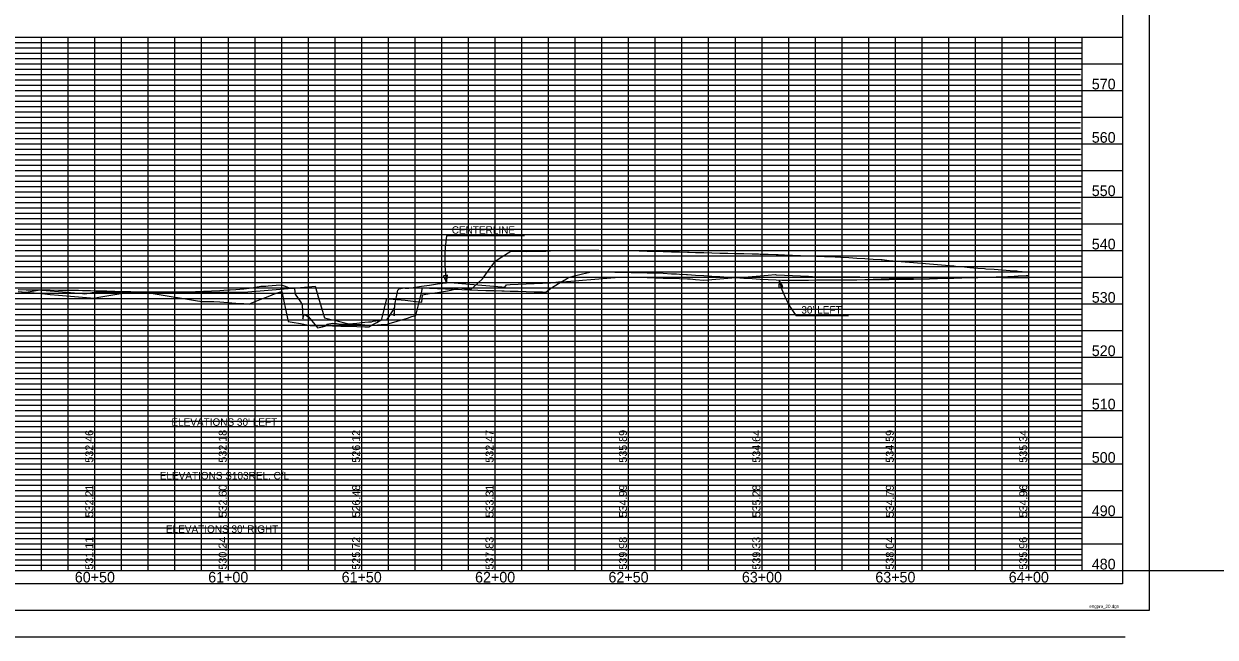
# Model space of a CAD drawing. Extents: x 178884 to 181858, y 178732 to 179192.
# Drawn here: x 179181.1 to 179627.5, y 178732.4 to 178962.4 of the extents above; entities that cross this region are included whole.
import ezdxf

# ---------------------------------------------------------------- set-up
doc = ezdxf.new("R2010")
doc.units = 0
for name, color, linetype in [('RD_DDB_ElevTX', 7, 'Continuous'), ('RD_DDB_Profile_EX', 7, 'Continuous'), ('RD_DDB_StaTX', 7, 'Continuous'), ('RD_DDB_StripGrade', 7, 'Continuous'), ('RD_GPK_Profile_Cell', 7, 'Continuous'), ('RD_SHT_Bndy', 7, 'Continuous'), ('RD_SHT_IplotShp', 7, 'Continuous'), ('RD_SHT_MjGrid', 7, 'Continuous'), ('RD_SHT_MnGrid', 7, 'Continuous'), ('RD_SHT_SubGrid', 7, 'Continuous'), ('RD_SHT_TX', 7, 'Continuous'), ('RD_TX_Profile', 7, 'Continuous')]:
    doc.layers.add(name, color=color, linetype=linetype)

msp = doc.modelspace()

# ---------------------------------------------------------------- linework, layer by layer
at = {"layer": 'RD_DDB_Profile_EX'}
for points in [[(179342.12, 178862.82), (179344.19, 178863.42), (179345.14, 178863.28), (179348.16, 178862.84), (179348.58, 178862.78), (179351.19, 178865.18), (179352.91, 178866.77), (179354.21, 178868.52), (179357.23, 178872.6), (179358.02, 178873.67), (179360.25, 178875.06), (179363.54, 178877.12), (179364.34, 178877.12), (179366.3, 178877.09), (179369.32, 178877.06), (179372.35, 178877.08), (179375.37, 178877.1), (179376.73, 178877.11), (179378.39, 178877.23), (179380.1, 178877.37), (179381.41, 178877.39), (179384.44, 178877.45), (179387.46, 178877.5), (179390.75, 178877.56), (179393.51, 178877.53), (179396.53, 178877.49), (179399.55, 178877.45), (179402.57, 178877.41), (179403.51, 178877.4), (179405.11, 178877.43), (179405.6, 178877.42), (179408.62, 178877.33), (179411.64, 178877.25), (179414.67, 178877.17), (179417.69, 178877.08), (179420.71, 178877), (179423.74, 178876.92), (179426.76, 178876.84), (179429.78, 178876.76), (179430.37, 178876.74), (179432.8, 178876.68), (179435.83, 178876.6), (179438.85, 178876.52), (179441.87, 178876.45), (179444.9, 178876.37), (179447.36, 178876.31), (179447.92, 178876.3), (179450.94, 178876.22), (179453.96, 178876.15), (179454.75, 178876.13), (179456.39, 178876.09), (179456.99, 178876.07), (179460.01, 178875.98), (179463.03, 178875.88), (179463.7, 178875.86), (179466.06, 178875.77), (179469.08, 178875.65), (179472.1, 178875.54), (179475.12, 178875.42), (179478.15, 178875.3), (179481.17, 178875.19), (179482.28, 178875.15), (179482.99, 178875.13), (179484.19, 178875.08), (179485.13, 178875.04), (179487.22, 178874.91), (179490.24, 178874.73), (179493.26, 178874.54), (179496.28, 178874.37), (179499.31, 178874.19), (179502.33, 178874.02), (179502.73, 178874), (179504.43, 178873.79), (179505.35, 178873.7), (179508.38, 178873.41), (179511.4, 178873.14), (179514.42, 178872.87), (179517.45, 178872.61), (179520.47, 178872.35), (179523.49, 178872.1), (179526.51, 178871.85), (179529.54, 178871.6), (179530.22, 178871.55), (179532.56, 178871.34), (179535.58, 178871.07), (179538.61, 178870.81), (179541.07, 178870.61), (179541.63, 178870.56), (179544.65, 178870.33), (179547.67, 178870.11), (179550.7, 178869.89), (179553.2, 178869.71), (179553.72, 178869.66), (179556.74, 178869.39), (179557.57, 178869.31)], [(179330.03, 178863.97), (179333.05, 178864.4), (179336.07, 178864.84), (179339.09, 178865.27), (179339.45, 178865.32), (179340.34, 178865.42), (179342.33, 178865.21), (179345.14, 178864.99), (179348.16, 178864.76), (179351.19, 178864.52), (179354.21, 178864.28), (179357.23, 178864.03), (179360.25, 178863.79), (179361.35, 178863.7), (179361.95, 178864.53), (179363.28, 178864.6), (179366.3, 178864.74), (179369.32, 178864.89), (179372.35, 178865.03), (179375.37, 178865.18), (179378.39, 178865.32), (179381.41, 178865.6), (179384.44, 178865.8), (179387.65, 178866.02), (179390.48, 178866.26), (179393.51, 178866.52), (179396.53, 178866.78), (179399.55, 178867.04), (179402.68, 178867.3), (179405.6, 178867.34), (179408.62, 178867.38), (179411.14, 178867.42), (179411.64, 178867.4), (179414.67, 178867.29), (179417.69, 178867.18), (179420.71, 178867.07), (179423.74, 178866.96), (179426.76, 178866.85), (179429.78, 178866.74), (179430.71, 178866.71), (179432.8, 178866.55), (179435.83, 178866.32), (179438.85, 178866.55), (179441.87, 178866.77), (179444.9, 178867), (179447.92, 178867.22), (179450.94, 178867.45), (179453.96, 178867.68), (179456.99, 178867.91), (179460.01, 178868.14), (179462.68, 178868.34), (179463.03, 178868.32), (179466.06, 178868.17), (179469.08, 178868.02), (179472.1, 178867.87), (179475.12, 178867.72), (179478.15, 178867.57), (179479.22, 178867.52), (179481.17, 178867.52), (179484.19, 178867.51), (179487.22, 178867.5), (179490.24, 178867.49), (179493.26, 178867.49), (179494.33, 178867.48), (179496.28, 178867.41), (179499.31, 178867.28), (179502.33, 178867.16), (179505.35, 178867.04), (179506.36, 178867), (179508.38, 178866.97), (179511.4, 178866.92), (179514.42, 178866.87), (179517.45, 178866.82), (179518.53, 178866.81), (179520.47, 178866.86), (179523.49, 178866.95), (179526.51, 178867.04), (179529.54, 178867.13), (179532.56, 178867.22), (179535.58, 178867.32), (179538.11, 178867.39), (179538.61, 178867.39), (179541.63, 178867.36), (179544.65, 178867.33), (179547.67, 178867.3), (179550.87, 178867.26), (179553.72, 178867.28), (179556.74, 178867.31), (179557.57, 178867.31)], [(179376.69, 178861.83), (179378.39, 178863.17), (179378.75, 178863.45), (179381.41, 178865.01), (179384.44, 178866.78), (179385.58, 178867.45), (179387.46, 178867.91), (179390.48, 178868.66), (179393.81, 178869.42), (179394.31, 178869.43), (179396.53, 178869.39), (179399.55, 178869.33), (179402.57, 178869.27), (179405.6, 178869.21), (179408.62, 178869.16), (179411.64, 178869.1), (179414.67, 178869.04), (179417.69, 178868.99), (179418.31, 178868.98), (179420.71, 178868.85), (179423.74, 178868.69), (179425.63, 178868.59), (179426.76, 178868.53), (179429.42, 178868.38), (179429.78, 178868.36), (179432.8, 178868.18), (179435.83, 178867.99), (179438.85, 178867.81), (179441.87, 178867.62), (179444.9, 178867.44), (179447.92, 178867.25), (179450.94, 178867.07), (179453.96, 178866.88), (179456.99, 178866.7), (179460.01, 178866.52), (179463.03, 178866.34), (179465.11, 178866.21), (179466.06, 178866.22), (179468.16, 178866.25), (179469.08, 178866.25), (179472.1, 178866.28), (179475.12, 178866.31), (179478.15, 178866.33), (179481.17, 178866.36), (179484.19, 178866.38), (179487.22, 178866.41), (179490.24, 178866.43), (179493.26, 178866.45), (179496.28, 178866.48), (179497.75, 178866.49), (179499.31, 178866.5), (179502.33, 178866.52), (179505.36, 178866.55), (179508.38, 178866.58), (179511.4, 178866.62), (179513.52, 178866.64), (179514.42, 178866.67), (179517.45, 178866.74), (179520.47, 178866.82), (179523.49, 178866.9), (179526.51, 178866.98), (179529.54, 178867.06), (179532.56, 178867.14), (179535.58, 178867.22), (179538.61, 178867.3), (179541.63, 178867.37), (179544.65, 178867.45), (179545.48, 178867.47), (179547.79, 178867.53), (179548.13, 178867.52), (179549.85, 178867.64), (179550.7, 178867.68), (179553.72, 178867.86), (179556.74, 178868.03), (179557.57, 178868.07)], [(179178.88, 178862.74), (179181.9, 178862.7), (179184.93, 178862.67), (179187.95, 178862.63), (179190.97, 178862.59), (179193.99, 178862.56), (179197.02, 178862.52), (179200.04, 178862.48), (179201.49, 178862.47), (179203.06, 178862.43), (179206.09, 178862.36), (179209.11, 178862.29), (179212.13, 178862.21), (179215.15, 178862.14), (179218.18, 178862.07), (179221.2, 178861.99), (179222.93, 178861.95), (179224.22, 178861.95), (179227.25, 178861.94), (179230.27, 178861.92), (179233.29, 178861.91), (179236.32, 178861.9), (179237.91, 178861.89), (179239.34, 178861.88), (179242.36, 178861.86), (179245.38, 178861.84), (179248.41, 178861.82), (179251.43, 178861.79), (179254.45, 178861.77), (179257.48, 178861.75), (179260.5, 178861.73), (179262.7, 178861.73), (179263.02, 178861.75), (179263.52, 178861.79), (179266.54, 178862.04), (179269.57, 178862.29), (179272.59, 178862.55), (179275.61, 178862.8), (179278.64, 178863.05), (179281.66, 178863.3), (179284.68, 178863.56), (179287.7, 178863.81), (179290.22, 178864.02), (179290.73, 178862.23), (179291.35, 178860.04), (179293.75, 178852.1), (179296.77, 178851.44), (179297.48, 178851.29), (179299.8, 178850.63), (179302.82, 178849.84), (179305.84, 178849.71), (179308.86, 178849.58), (179312.15, 178849.44), (179314.91, 178849.59), (179316.91, 178849.69), (179317.93, 178849.99), (179320.96, 178850.9), (179323.98, 178851.81), (179324.85, 178852.07), (179326.51, 178852.59), (179327, 178852.73), (179327.99, 178853), (179330.03, 178861.57), (179330.45, 178863.38), (179333.05, 178863.28), (179336.07, 178863.16), (179339.09, 178863.03), (179342.12, 178862.91), (179345.14, 178862.79), (179348.16, 178862.66), (179351.19, 178862.54), (179354.21, 178862.42), (179354.81, 178862.39), (179356.41, 178862.38), (179357.23, 178862.35), (179360.25, 178862.26), (179361.09, 178862.23), (179363.28, 178862.18), (179366.3, 178862.1), (179369.32, 178862.02), (179372.35, 178861.94), (179375.37, 178861.86), (179376.69, 178861.83)], [(179180.16, 178861.5), (179181.9, 178861.78), (179184.93, 178862.26), (179187.21, 178862.63), (179187.95, 178862.57), (179190.97, 178862.3), (179193.99, 178862.04), (179197.02, 178861.78), (179200.04, 178861.52), (179203.06, 178861.26), (179203.9, 178861.19), (179206.09, 178861.56), (179208.03, 178861.89), (179209.11, 178861.89), (179212.13, 178861.87), (179215.15, 178861.86), (179218.18, 178861.85), (179221.2, 178861.83), (179224.48, 178861.82), (179227.25, 178861.81), (179230.27, 178861.79), (179233.29, 178861.78), (179235.9, 178861.77), (179236.32, 178861.77), (179239.34, 178861.75), (179240.61, 178861.74), (179242.36, 178861.83), (179245.38, 178861.98), (179248.41, 178862.13), (179251.43, 178862.29), (179254.45, 178862.44), (179257.48, 178862.59), (179258.41, 178862.64), (179260.5, 178862.79), (179263.52, 178863.02), (179264.56, 178863.09), (179266.54, 178863.42), (179269.83, 178863.96), (179271.73, 178864.07), (179272.59, 178864.13), (179275.61, 178864.35), (179277.45, 178864.48), (179278.64, 178864.08), (179280.88, 178863.31), (179281.66, 178863.28), (179282.55, 178863.25), (179282.59, 178861.66), (179282.78, 178861), (179284.68, 178858.16), (179285.35, 178857.16), (179285.55, 178851.73), (179286.06, 178853.52), (179287.7, 178852.54), (179290.73, 178848.87), (179291.1, 178848.42), (179292.95, 178848.71), (179293.89, 178848.99), (179294.74, 178849.81), (179296.77, 178850.2), (179298.23, 178850.07), (179299.8, 178849.81), (179301.1, 178849.77), (179302.82, 178849.93), (179305.84, 178850.2), (179308.86, 178850.47), (179310.25, 178850.59), (179311.3, 178850.68), (179312.01, 178850.9), (179314.91, 178851.26), (179317.19, 178851.55), (179317.93, 178852.66), (179319.36, 178854.81), (179319.87, 178855.95), (179319.9, 178852.94), (179320.15, 178857.02), (179321.25, 178862.55), (179321.67, 178863.04), (179323.6, 178863.34), (179323.98, 178863.33), (179325.31, 178863.28), (179327, 178863.53), (179330.03, 178863.97)], [(179178.88, 178861.97), (179181.9, 178861.71), (179184.93, 178861.46), (179187.95, 178861.21), (179190.97, 178860.95), (179193.99, 178860.7), (179197.02, 178860.44), (179200.04, 178860.19), (179203.06, 178859.93), (179206.09, 178859.68), (179207.35, 178859.57), (179209.11, 178859.87), (179212.13, 178860.37), (179215.15, 178860.87), (179218.18, 178861.38), (179220.45, 178861.75), (179221.2, 178861.75), (179224.22, 178861.74), (179226.92, 178861.72), (179227.25, 178861.67), (179230.27, 178861.17), (179233.29, 178860.67), (179236.32, 178860.17), (179239.34, 178859.68), (179242.36, 178859.18), (179245.38, 178858.68), (179247.71, 178858.29), (179248.41, 178858.28), (179251.43, 178858.25), (179252.27, 178858.24), (179254.45, 178858.09), (179257.48, 178857.88), (179260.5, 178857.67), (179263.52, 178857.46), (179265.46, 178857.33), (179266.54, 178857.76), (179269.57, 178858.97), (179272.59, 178860.17), (179275.61, 178861.37), (179277.69, 178861.98), (179278.64, 178857.71), (179280.16, 178850.83), (179281.66, 178850.54), (179284.68, 178849.97), (179287.7, 178849.41), (179288.31, 178849.29), (179290.73, 178849.27), (179292.67, 178849.25), (179293.75, 178849.22), (179296.77, 178849.14), (179299.8, 178849.05), (179302.82, 178848.96), (179305.84, 178848.88), (179308.86, 178848.79), (179310.3, 178848.75), (179311.89, 178849.6), (179313.38, 178850.41), (179314.91, 178851.39), (179315.26, 178851.62), (179317.1, 178859.41), (179317.93, 178859.33), (179320.96, 178859.03), (179323.98, 178858.72), (179327, 178858.4), (179330.19, 178858.05), (179330.41, 178860.8), (179333.05, 178861.21), (179336.07, 178861.68), (179339.09, 178862.15), (179341.2, 178862.56), (179342.12, 178862.82)]]:
    msp.add_lwpolyline(points, dxfattribs=at)
at = {"layer": 'RD_GPK_Profile_Cell'}
msp.add_line((178957.57, 178757.39), (181857.57, 178757.39), dxfattribs=at)
at = {"layer": 'RD_SHT_Bndy'}
for p, q in [((178922.77, 178957.39), (179592.77, 178957.39)), ((179577.57, 178957.39), (179577.57, 178757.39)), ((178922.77, 178757.39), (179592.77, 178757.39)), ((179593.83, 178742.39), (178889.83, 178742.39)), ((179593.83, 178732.39), (178889.83, 178732.39))]:
    msp.add_line(p, q, dxfattribs=at)
msp.add_lwpolyline([(178922.77, 179172.39), (179592.77, 179172.39), (179592.77, 178752.39), (178922.77, 178752.39)], close=True, dxfattribs=at)
at = {"layer": 'RD_SHT_IplotShp'}
msp.add_lwpolyline([(178884.41, 179182.39), (179602.77, 179182.39), (179602.77, 178742.39), (178884.41, 178742.39)], close=True, dxfattribs=at)
at = {"layer": 'RD_SHT_MjGrid'}
for p, q in [((179197.57, 178957.39), (179197.57, 178757.39)), ((179217.57, 178957.39), (179217.57, 178757.39)), ((179237.57, 178957.39), (179237.57, 178757.39)), ((179257.57, 178957.39), (179257.57, 178757.39)), ((179277.57, 178957.39), (179277.57, 178757.39)), ((179297.57, 178957.39), (179297.57, 178757.39)), ((179317.57, 178957.39), (179317.57, 178757.39)), ((179337.57, 178957.39), (179337.57, 178757.39)), ((179357.57, 178957.39), (179357.57, 178757.39)), ((179377.57, 178957.39), (179377.57, 178757.39)), ((179397.57, 178957.39), (179397.57, 178757.39)), ((179417.57, 178957.39), (179417.57, 178757.39)), ((179437.57, 178957.39), (179437.57, 178757.39)), ((179457.57, 178957.39), (179457.57, 178757.39)), ((179477.57, 178957.39), (179477.57, 178757.39)), ((179497.57, 178957.39), (179497.57, 178757.39)), ((179517.57, 178957.39), (179517.57, 178757.39)), ((179537.57, 178957.39), (179537.57, 178757.39)), ((179557.57, 178957.39), (179557.57, 178757.39)), ((178922.77, 178937.39), (179592.77, 178937.39)), ((178922.77, 178917.39), (179592.77, 178917.39)), ((178922.77, 178897.39), (179592.77, 178897.39)), ((178922.77, 178877.39), (179592.77, 178877.39)), ((178922.77, 178857.39), (179592.77, 178857.39)), ((178922.77, 178837.39), (179592.77, 178837.39)), ((178922.77, 178817.39), (179592.77, 178817.39)), ((178922.77, 178797.39), (179592.77, 178797.39)), ((178922.77, 178777.39), (179592.77, 178777.39))]:
    msp.add_line(p, q, dxfattribs=at)
at = {"layer": 'RD_SHT_MnGrid'}
for p, q in [((179187.57, 178957.39), (179187.57, 178757.39)), ((179207.57, 178957.39), (179207.57, 178757.39)), ((179227.57, 178957.39), (179227.57, 178757.39)), ((179247.57, 178957.39), (179247.57, 178757.39)), ((179267.57, 178957.39), (179267.57, 178757.39)), ((179287.57, 178957.39), (179287.57, 178757.39)), ((179307.57, 178957.39), (179307.57, 178757.39)), ((179327.57, 178957.39), (179327.57, 178757.39)), ((179347.57, 178957.39), (179347.57, 178757.39)), ((179367.57, 178957.39), (179367.57, 178757.39)), ((179387.57, 178957.39), (179387.57, 178757.39)), ((179407.57, 178957.39), (179407.57, 178757.39)), ((179427.57, 178957.39), (179427.57, 178757.39)), ((179447.57, 178957.39), (179447.57, 178757.39)), ((179467.57, 178957.39), (179467.57, 178757.39)), ((179487.57, 178957.39), (179487.57, 178757.39)), ((179507.57, 178957.39), (179507.57, 178757.39)), ((179527.57, 178957.39), (179527.57, 178757.39)), ((179547.57, 178957.39), (179547.57, 178757.39)), ((179567.57, 178957.39), (179567.57, 178757.39)), ((178922.77, 178947.39), (179592.77, 178947.39)), ((178922.77, 178927.39), (179592.77, 178927.39)), ((178922.77, 178907.39), (179592.77, 178907.39)), ((178922.77, 178887.39), (179592.77, 178887.39)), ((178922.77, 178867.39), (179592.77, 178867.39)), ((178922.77, 178847.39), (179592.77, 178847.39)), ((178922.77, 178827.39), (179592.77, 178827.39)), ((178922.77, 178807.39), (179592.77, 178807.39)), ((178922.77, 178787.39), (179592.77, 178787.39)), ((178922.77, 178767.39), (179592.77, 178767.39))]:
    msp.add_line(p, q, dxfattribs=at)
at = {"layer": 'RD_SHT_SubGrid'}
for p, q in [((178937.59, 178955.39), (179577.49, 178955.39)), ((178937.59, 178953.39), (179577.27, 178953.39)), ((178937.59, 178951.39), (179577.49, 178951.39)), ((178937.61, 178949.39), (179577.49, 178949.39)), ((178937.59, 178945.39), (179577.49, 178945.39)), ((178937.59, 178943.39), (179577.07, 178943.39)), ((178937.59, 178941.39), (179577.27, 178941.39)), ((178937.59, 178939.39), (179577.49, 178939.39)), ((178937.59, 178935.39), (179577.49, 178935.39)), ((178937.59, 178933.39), (179577.49, 178933.39)), ((178937.59, 178931.39), (179577.27, 178931.39)), ((178937.59, 178929.39), (179577.49, 178929.39)), ((178937.59, 178925.39), (179577.07, 178925.39)), ((178937.59, 178923.39), (179577.07, 178923.39)), ((178937.59, 178921.39), (179577.27, 178921.39)), ((178937.59, 178919.39), (179577.27, 178919.39)), ((178937.59, 178915.39), (179577.07, 178915.39)), ((178937.59, 178913.39), (179577.27, 178913.39)), ((178937.59, 178911.39), (179577.07, 178911.39)), ((178937.61, 178909.39), (179577.49, 178909.39)), ((178937.59, 178905.39), (179577.27, 178905.39)), ((178937.59, 178903.39), (179577.27, 178903.39)), ((178937.59, 178901.39), (179577.27, 178901.39)), ((178937.59, 178899.39), (179577.27, 178899.39)), ((178937.63, 178895.39), (179577.07, 178895.39)), ((178937.61, 178891.39), (179577.27, 178891.39)), ((178937.63, 178893.39), (179577.07, 178893.39)), ((178937.61, 178889.39), (179577.27, 178889.39)), ((178937.59, 178885.39), (179577.27, 178885.39)), ((178937.59, 178883.39), (179577.27, 178883.39)), ((178937.59, 178881.39), (179577.07, 178881.39)), ((178937.59, 178879.39), (179577.27, 178879.39)), ((178937.59, 178879.39), (179577.27, 178879.39)), ((178937.59, 178875.39), (179577.49, 178875.39)), ((178937.59, 178873.39), (179577.49, 178873.39)), ((178937.59, 178871.39), (179577.49, 178871.39)), ((178937.59, 178869.39), (179577.49, 178869.39)), ((178937.59, 178865.39), (179577.49, 178865.39)), ((178937.59, 178863.39), (179577.49, 178863.39)), ((178937.59, 178861.39), (179577.49, 178861.39)), ((178937.59, 178859.39), (179577.49, 178859.39)), ((178937.59, 178855.39), (179577.51, 178855.39)), ((178937.59, 178853.39), (179577.51, 178853.39)), ((178937.59, 178851.39), (179577.51, 178851.39)), ((178937.59, 178849.39), (179577.51, 178849.39)), ((178937.59, 178845.39), (179577.51, 178845.39)), ((178937.59, 178843.39), (179577.51, 178843.39)), ((178937.59, 178841.39), (179577.51, 178841.39)), ((178937.59, 178839.39), (179577.51, 178839.39)), ((178937.59, 178835.39), (179577.51, 178835.39)), ((178937.59, 178833.39), (179577.51, 178833.39)), ((178937.59, 178831.39), (179577.51, 178831.39)), ((178937.59, 178829.39), (179577.51, 178829.39)), ((178937.59, 178825.39), (179577.51, 178825.39)), ((178937.59, 178823.39), (179577.51, 178823.39)), ((178937.61, 178825.39), (179577.51, 178825.39)), ((178937.61, 178821.39), (179577.41, 178821.39)), ((178937.61, 178819.39), (179577.41, 178819.39)), ((178937.61, 178815.39), (179577.49, 178815.39)), ((178937.59, 178813.39), (179577.55, 178813.39)), ((178937.59, 178811.39), (179577.55, 178811.39)), ((178937.59, 178805.39), (179577.55, 178805.39)), ((178937.61, 178809.39), (179577.55, 178809.39)), ((178937.59, 178803.39), (179577.55, 178803.39)), ((178937.59, 178801.39), (179577.55, 178801.39)), ((178937.61, 178799.39), (179577.55, 178799.39)), ((178937.59, 178795.39), (179577.55, 178795.39)), ((178937.59, 178793.39), (179577.55, 178793.39)), ((178937.59, 178791.39), (179577.55, 178791.39)), ((178937.59, 178789.39), (179577.51, 178789.39)), ((178937.59, 178783.39), (179577.51, 178783.39)), ((178937.61, 178785.39), (179577.41, 178785.39)), ((178937.59, 178781.39), (179577.51, 178781.39)), ((178937.59, 178779.39), (179577.51, 178779.39)), ((178937.63, 178775.39), (179577.51, 178775.39)), ((178937.59, 178773.39), (179577.51, 178773.39)), ((178937.59, 178771.39), (179577.51, 178771.39)), ((178937.59, 178769.39), (179577.51, 178769.39)), ((178937.63, 178765.39), (179577.51, 178765.39)), ((178937.63, 178763.39), (179577.51, 178763.39)), ((178937.63, 178761.39), (179577.51, 178761.39)), ((178937.63, 178759.39), (179577.51, 178759.39))]:
    msp.add_line(p, q, dxfattribs=at)
at = {"layer": 'RD_TX_Profile'}
for p, q in [((179368.68, 178882.89), (179339.43, 178882.89)), ((179490.09, 178852.94), (179470.43, 178852.94))]:
    msp.add_line(p, q, dxfattribs=at)
for points in [[(179338.35, 178867.9), (179339.45, 178865.32), (179339.79, 178868.1)], [(179465.45, 178863.83), (179464.07, 178866.27), (179464.04, 178863.47)]]:
    msp.add_lwpolyline(points, close=True, dxfattribs=at)
for centre, radius, start, end in [((179402.26, 178874.18), 63.43, 172.1051, 188.0276), ((179501.32, 178875.86), 38.46, 194.4297, 216.5746)]:
    msp.add_arc(centre, radius, start, end, dxfattribs=at)

# ---------------------------------------------------------------- texts
at = {"layer": 'RD_DDB_ElevTX'}
for s, p in [('570', (179581.28, 178937.79)), ('560', (179581.28, 178917.79)), ('550', (179581.28, 178897.79)), ('540', (179581.28, 178877.79)), ('530', (179581.28, 178857.79)), ('520', (179581.28, 178837.79)), ('510', (179581.28, 178817.79)), ('500', (179581.28, 178797.79)), ('490', (179581.28, 178777.79)), ('480', (179581.28, 178757.79))]:
    msp.add_text(s, height=4, dxfattribs=at).set_placement(p)
at = {"layer": 'RD_DDB_StaTX'}
for s, p in [('60+50', (179200.16, 178752.89)), ('61+00', (179250.16, 178752.89)), ('61+50', (179300.16, 178752.89)), ('62+00', (179350.16, 178752.89)), ('62+50', (179400.16, 178752.89)), ('63+00', (179450.16, 178752.89)), ('63+50', (179500.16, 178752.89)), ('64+00', (179550.16, 178752.89))]:
    msp.add_text(s, height=4, dxfattribs=at).set_placement(p)
at = {"layer": 'RD_DDB_StripGrade'}
for s, p in [('532.46', (179207.07, 178797.84)), ('532.18', (179257.07, 178797.84)), ('526.12', (179307.07, 178797.84)), ('532.47', (179357.07, 178797.84)), ('535.89', (179407.07, 178797.84)), ('534.64', (179457.07, 178797.84)), ('534.59', (179507.07, 178797.84)), ('535.34', (179557.07, 178797.84)), ('532.21', (179207.1, 178777.31)), ('532.60', (179257.1, 178777.31)), ('526.48', (179307.1, 178777.31)), ('533.31', (179357.1, 178777.31)), ('534.99', (179407.1, 178777.31)), ('535.28', (179457.1, 178777.31)), ('534.79', (179507.1, 178777.31)), ('534.96', (179557.1, 178777.31)), ('531.11', (179207.07, 178757.75)), ('530.24', (179257.07, 178757.75)), ('525.72', (179307.07, 178757.75)), ('537.83', (179357.07, 178757.75)), ('539.98', (179407.07, 178757.75)), ('539.33', (179457.07, 178757.75)), ('538.04', (179507.07, 178757.75)), ('535.96', (179557.07, 178757.75))]:
    msp.add_text(s, height=3, rotation=90, dxfattribs=at).set_placement(p)
at = {"layer": 'RD_SHT_TX'}
msp.add_text('engpro_20.dgn', height=1.2, dxfattribs=at).set_placement((179580.35, 178743.37))
at = {"layer": 'RD_TX_Profile'}
for s, p in [('CENTERLINE', (179341.43, 178883.69)), ("30' LEFT", (179472.43, 178853.74)), ("ELEVATIONS 30' LEFT", (179236.36, 178811.66)), ('ELEVATIONS S103REL. C/L', (179231.99, 178791.56)), ("ELEVATIONS 30' RIGHT", (179234.31, 178771.53))]:
    msp.add_text(s, height=2.8, dxfattribs=at).set_placement(p)

doc.saveas('drawing.dxf')
